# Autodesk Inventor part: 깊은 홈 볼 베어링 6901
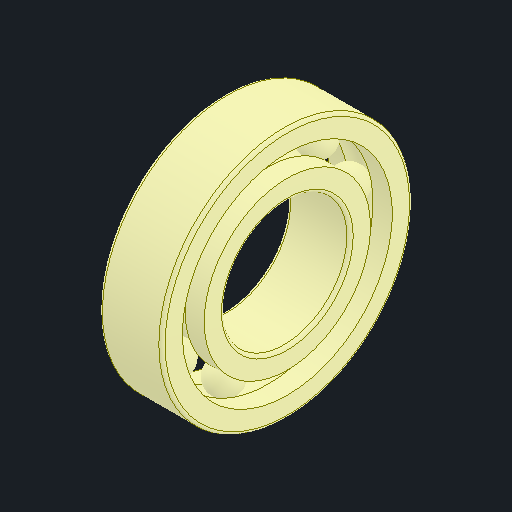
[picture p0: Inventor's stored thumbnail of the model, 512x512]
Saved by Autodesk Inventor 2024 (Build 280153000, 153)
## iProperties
Created: 2024-05
Part Number: 깊은 홈 볼 베어링 6901
Material: 강철, 연강
Description: 깊은 그루브 볼 베어링
Document SubType Name: Modeling
Designer: kh_501
Density: 7.85 g/cm^3
Appearance: 기본값
Author: jhkim
Sending System: Autodesk Inventor 2025
Preprocessor: ST-DEVELOPER v20
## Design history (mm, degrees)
feature "Solid1"
feature "Solid1:1"
feature "Solid1:2"
feature "Solid1:3"
feature "Solid1:4"
feature "Solid1:5"
feature "Solid1:6"
feature "Solid1:7"
feature "Solid1:8"
feature "Solid1:9"
feature "Solid1:10"
node "솔리드1"
node "솔리드2"
node "솔리드3"
node "솔리드4"
node "솔리드5"
node "솔리드6"
node "솔리드7"
node "솔리드8"
node "솔리드9"
node "솔리드10"
node "솔리드11"
